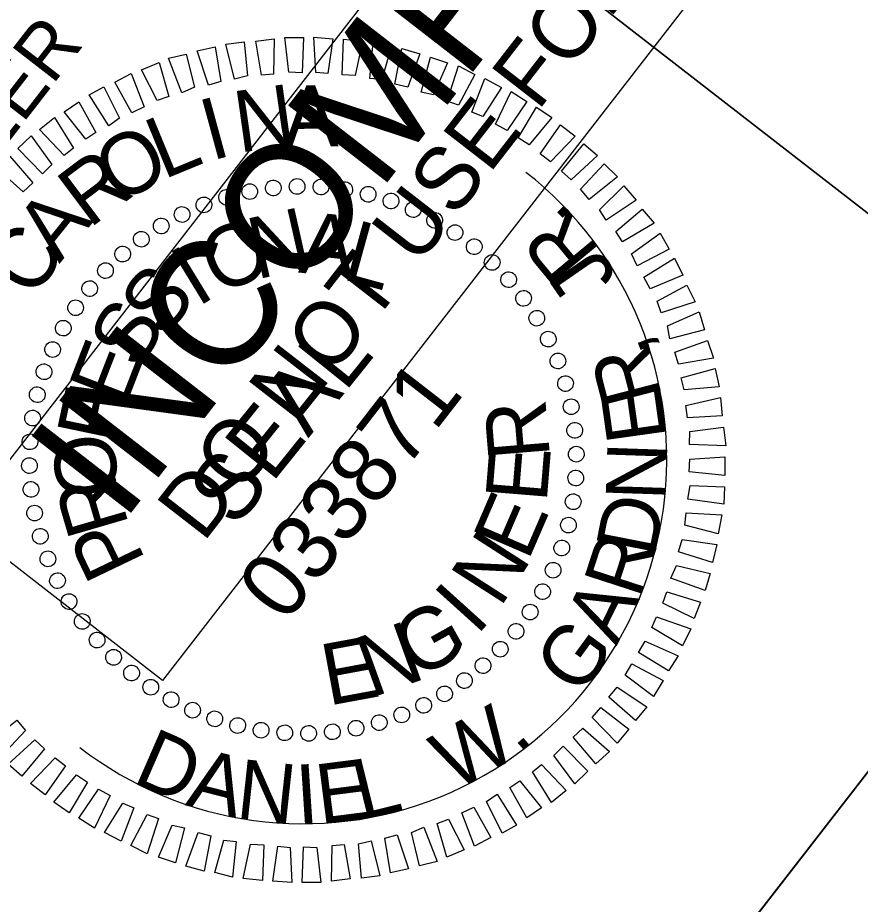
# Model space of a CAD drawing. Extents: x 2013373 to 2015284, y 444589 to 446636.
# Drawn here: x 2014373.4 to 2014450.7, y 446385.3 to 446466.6 of the extents above; entities that cross this region are included whole.
import ezdxf

# ---------------------------------------------------------------- set-up
doc = ezdxf.new("R2010")
doc.units = 0
for name, color, linetype in [('Scratch_Level_0', 7, 'Continuous'), ('Sheet Plan And Profile CELL', 7, 'Continuous'), ('Sheet Professional Seal CELL', 7, 'Continuous'), ('Sheet Profile Grid Minor CELL', 7, 'Continuous'), ('Sheet Sticker Exception Certification CELL', 7, 'Continuous'), ('Sheet Sticker Incomplete CELL', 7, 'Continuous')]:
    doc.layers.add(name, color=color, linetype=linetype)

msp = doc.modelspace()

# ---------------------------------------------------------------- linework, layer by layer
at = {"layer": 'Scratch_Level_0'}
msp.add_arc((2014399.595, 446426.074), 33.364, 232.2051, 52.2051, dxfattribs=at)
at = {"layer": 'Sheet Plan And Profile CELL'}
msp.add_line((2014387.32, 446498.401), (2014476.179, 446429.487), dxfattribs=at)
for points in [[(2014387.32, 446498.401), (2014448.604, 446577.422), (2014537.502, 446508.477), (2014476.219, 446429.457)], [(2014326.006, 446419.34), (2014387.32, 446498.401), (2014476.219, 446429.457), (2014414.904, 446350.396)]]:
    msp.add_lwpolyline(points, close=True, dxfattribs=at)
at = {"layer": 'Sheet Professional Seal CELL'}
for p, q in [((2014394.732, 446450.726), (2014394.732, 446450.726)), ((2014396.867, 446451.032), (2014396.867, 446451.032)), ((2014399.09, 446451.206), (2014399.09, 446451.206)), ((2014401.239, 446451.121), (2014401.239, 446451.121)), ((2014403.445, 446450.865), (2014403.445, 446450.865)), ((2014405.599, 446450.461), (2014405.599, 446450.461)), ((2014392.593, 446450.171), (2014392.593, 446450.171)), ((2014407.67, 446449.867), (2014407.67, 446449.867)), ((2014390.502, 446449.514), (2014390.502, 446449.514)), ((2014409.697, 446449.054), (2014409.697, 446449.054)), ((2014388.517, 446448.586), (2014388.517, 446448.586)), ((2014411.68, 446448.022), (2014411.68, 446448.022)), ((2014386.58, 446447.557), (2014386.58, 446447.557)), ((2014413.563, 446446.942), (2014413.563, 446446.942)), ((2014384.74, 446446.327), (2014384.74, 446446.327)), ((2014415.332, 446445.633), (2014415.332, 446445.633)), ((2014383.097, 446444.943), (2014383.097, 446444.943)), ((2014416.979, 446444.166), (2014416.979, 446444.166)), ((2014381.503, 446443.459), (2014381.503, 446443.459)), ((2014418.463, 446442.572), (2014418.463, 446442.572)), ((2014380.036, 446441.812), (2014380.036, 446441.812)), ((2014419.847, 446440.929), (2014419.847, 446440.929)), ((2014378.727, 446440.043), (2014378.727, 446440.043)), ((2014421.078, 446439.089), (2014421.078, 446439.089)), ((2014377.647, 446438.16), (2014377.647, 446438.16)), ((2014422.106, 446437.152), (2014422.106, 446437.152)), ((2014376.615, 446436.177), (2014376.615, 446436.177)), ((2014423.034, 446435.167), (2014423.034, 446435.167)), ((2014375.802, 446434.15), (2014375.802, 446434.15)), ((2014423.691, 446433.076), (2014423.691, 446433.076)), ((2014375.208, 446432.079), (2014375.208, 446432.079)), ((2014424.246, 446430.937), (2014424.246, 446430.937)), ((2014374.804, 446429.925), (2014374.804, 446429.925)), ((2014424.552, 446428.802), (2014424.552, 446428.802)), ((2014374.548, 446427.719), (2014374.548, 446427.719)), ((2014399.595, 446426.074), (2014399.595, 446426.074)), ((2014424.726, 446426.579), (2014424.726, 446426.579)), ((2014374.463, 446425.57), (2014374.463, 446425.57)), ((2014424.641, 446424.43), (2014424.641, 446424.43)), ((2014374.637, 446423.347), (2014374.637, 446423.347)), ((2014424.386, 446422.224), (2014424.386, 446422.224)), ((2014374.943, 446421.212), (2014374.943, 446421.212)), ((2014423.981, 446420.07), (2014423.981, 446420.07)), ((2014375.498, 446419.073), (2014375.498, 446419.073)), ((2014423.387, 446417.999), (2014423.387, 446417.999)), ((2014376.155, 446416.982), (2014376.155, 446416.982)), ((2014422.575, 446415.972), (2014422.575, 446415.972)), ((2014377.083, 446414.996), (2014377.083, 446414.996)), ((2014421.542, 446413.989), (2014421.542, 446413.989)), ((2014378.112, 446413.06), (2014378.112, 446413.06)), ((2014420.462, 446412.106), (2014420.462, 446412.106)), ((2014379.342, 446411.219), (2014379.342, 446411.219)), ((2014419.153, 446410.337), (2014419.153, 446410.337)), ((2014380.726, 446409.577), (2014380.726, 446409.577)), ((2014417.686, 446408.69), (2014417.686, 446408.69)), ((2014382.21, 446407.983), (2014382.21, 446407.983)), ((2014416.092, 446407.206), (2014416.092, 446407.206)), ((2014383.857, 446406.516), (2014383.857, 446406.516)), ((2014414.45, 446405.822), (2014414.45, 446405.822)), ((2014385.626, 446405.207), (2014385.626, 446405.207)), ((2014387.509, 446404.127), (2014387.509, 446404.127)), ((2014412.609, 446404.592), (2014412.609, 446404.592)), ((2014410.673, 446403.563), (2014410.673, 446403.563)), ((2014389.492, 446403.095), (2014389.492, 446403.095)), ((2014408.687, 446402.635), (2014408.687, 446402.635)), ((2014391.519, 446402.282), (2014391.519, 446402.282)), ((2014393.59, 446401.688), (2014393.59, 446401.688)), ((2014406.597, 446401.978), (2014406.597, 446401.978)), ((2014395.744, 446401.283), (2014395.744, 446401.283)), ((2014397.95, 446401.028), (2014397.95, 446401.028)), ((2014400.099, 446400.943), (2014400.099, 446400.943)), ((2014402.322, 446401.117), (2014402.322, 446401.117)), ((2014404.457, 446401.423), (2014404.457, 446401.423))]:
    msp.add_line(p, q, dxfattribs=at)
for points in [[(2014393.327, 446460.99), (2014392.529, 446464.203), (2014394.213, 446464.416), (2014394.502, 446461.281)], [(2014395.813, 446461.34), (2014395.274, 446464.479), (2014396.958, 446464.692), (2014396.905, 446461.442)], [(2014398.308, 446461.62), (2014397.94, 446464.816), (2014399.65, 446464.819), (2014399.527, 446461.56)], [(2014400.768, 446461.61), (2014400.61, 446464.833), (2014402.338, 446464.695), (2014401.887, 446461.502)], [(2014403.185, 446461.381), (2014403.308, 446464.64), (2014405.075, 446464.471), (2014404.404, 446461.321)], [(2014405.72, 446461.06), (2014406.053, 446464.345), (2014407.676, 446463.909), (2014406.839, 446460.952)], [(2014390.938, 446460.439), (2014389.899, 446463.586), (2014391.565, 446463.939), (2014392.074, 446460.76)], [(2014408.032, 446460.533), (2014408.655, 446463.783), (2014410.317, 446463.316), (2014409.208, 446460.254)], [(2014388.497, 446459.738), (2014387.277, 446462.898), (2014388.904, 446463.282), (2014389.645, 446460.24)], [(2014410.441, 446459.804), (2014411.282, 446463.011), (2014412.844, 446462.495), (2014411.577, 446459.555)], [(2014386.235, 446459.024), (2014384.81, 446461.838), (2014386.401, 446462.502), (2014387.291, 446459.407)], [(2014412.827, 446458.965), (2014413.88, 446462.199), (2014415.367, 446461.424), (2014413.872, 446458.598)], [(2014383.917, 446457.912), (2014382.351, 446460.707), (2014383.854, 446461.503), (2014385.025, 446458.444)], [(2014415.091, 446457.968), (2014416.271, 446461.04), (2014417.798, 446460.235), (2014416.105, 446457.562)], [(2014381.787, 446456.716), (2014380.003, 446459.555), (2014381.335, 446460.294), (2014382.768, 446457.41)], [(2014417.264, 446456.853), (2014418.702, 446459.85), (2014420.138, 446458.927), (2014418.335, 446456.276)], [(2014379.697, 446455.489), (2014377.707, 446457.982), (2014379.052, 446458.9), (2014380.617, 446456.105)], [(2014419.344, 446455.619), (2014421.02, 446458.433), (2014422.424, 446457.47), (2014420.354, 446454.963)], [(2014377.712, 446453.991), (2014375.451, 446456.378), (2014376.809, 446457.476), (2014378.553, 446454.668)], [(2014421.35, 446454.127), (2014423.223, 446456.787), (2014424.567, 446455.745), (2014422.299, 446453.391)], [(2014375.715, 446452.313), (2014373.462, 446454.63), (2014374.671, 446455.781), (2014376.569, 446453.17)], [(2014423.295, 446452.555), (2014425.366, 446455.062), (2014426.608, 446453.972), (2014424.182, 446451.741)], [(2014373.928, 446450.662), (2014371.483, 446452.812), (2014372.731, 446453.932), (2014374.822, 446451.488)], [(2014425.038, 446450.887), (2014427.237, 446453.232), (2014428.457, 446452.032), (2014425.834, 446449.954)], [(2014426.808, 446449.008), (2014429.024, 446451.213), (2014430.153, 446449.894), (2014427.393, 446448.049)], [(2014428.307, 446447.024), (2014430.72, 446449.075), (2014431.809, 446447.787), (2014428.891, 446446.064)], [(2014429.743, 446444.96), (2014432.354, 446446.858), (2014433.181, 446445.395), (2014430.236, 446443.882)], [(2014430.869, 446442.822), (2014433.678, 446444.567), (2014434.443, 446443.024), (2014431.432, 446441.752)], [(2014432.074, 446440.622), (2014434.808, 446442.108), (2014435.573, 446440.565), (2014432.457, 446439.566)], [(2014433.037, 446438.356), (2014435.938, 446439.649), (2014436.432, 446438.001), (2014433.258, 446437.172)], [(2014433.698, 446435.945), (2014436.696, 446437.037), (2014437.26, 446435.398), (2014434.051, 446434.849)], [(2014434.281, 446433.595), (2014437.415, 446434.455), (2014437.768, 446432.789), (2014434.563, 446432.491)], [(2014434.709, 446431.048), (2014437.892, 446431.807), (2014438.035, 446430.114), (2014434.851, 446429.926)], [(2014435.081, 446428.672), (2014438.168, 446429.062), (2014438.381, 446427.378), (2014435.052, 446427.492)], [(2014435.08, 446426.142), (2014438.294, 446426.37), (2014438.297, 446424.659), (2014435.012, 446424.993)], [(2014435.101, 446423.721), (2014438.25, 446423.62), (2014438.204, 446422.011), (2014434.901, 446422.484)], [(2014434.741, 446421.216), (2014438.008, 446421.024), (2014437.69, 446419.309), (2014434.633, 446420.098)], [(2014434.371, 446418.782), (2014437.565, 446418.33), (2014437.168, 446416.677), (2014434.053, 446417.637)], [(2014433.853, 446416.4), (2014436.941, 446415.65), (2014436.496, 446414.097), (2014433.324, 446415.228)], [(2014432.984, 446413.974), (2014436.059, 446413.044), (2014435.465, 446411.543), (2014432.617, 446412.93)], [(2014432.026, 446411.679), (2014435.159, 446410.578), (2014434.394, 446409.02), (2014431.581, 446410.696)], [(2014430.99, 446409.445), (2014434.009, 446408.117), (2014433.117, 446406.721), (2014430.373, 446408.405)], [(2014429.756, 446407.365), (2014432.622, 446405.839), (2014431.738, 446404.373), (2014429.14, 446406.325)], [(2014428.422, 446405.236), (2014431.143, 446403.442), (2014430.093, 446402.169), (2014427.647, 446404.319)], [(2014426.912, 446403.37), (2014429.48, 446401.379), (2014428.429, 446400.106), (2014426.137, 446402.453)], [(2014374.151, 446401.262), (2014371.953, 446398.917), (2014370.732, 446400.117), (2014373.356, 446402.195)], [(2014425.261, 446401.487), (2014427.707, 446399.337), (2014426.458, 446398.217), (2014424.368, 446400.661)], [(2014375.894, 446399.594), (2014373.823, 446397.087), (2014372.581, 446398.177), (2014375.007, 446400.408)], [(2014423.474, 446399.836), (2014425.727, 446397.519), (2014424.518, 446396.368), (2014422.62, 446398.979)], [(2014377.839, 446398.022), (2014375.966, 446395.362), (2014374.622, 446396.404), (2014376.891, 446398.757)], [(2014421.477, 446398.158), (2014423.739, 446395.771), (2014422.381, 446394.672), (2014420.636, 446397.481)], [(2014379.845, 446396.529), (2014378.169, 446393.716), (2014376.765, 446394.679), (2014378.836, 446397.186)], [(2014419.492, 446396.659), (2014421.482, 446394.167), (2014420.137, 446393.249), (2014418.572, 446396.044)], [(2014381.925, 446395.296), (2014380.487, 446392.298), (2014379.052, 446393.222), (2014380.855, 446395.873)], [(2014417.402, 446395.433), (2014419.187, 446392.594), (2014417.855, 446391.855), (2014416.421, 446394.739)], [(2014384.098, 446394.18), (2014382.918, 446391.109), (2014381.391, 446391.914), (2014383.084, 446394.587)], [(2014415.273, 446394.237), (2014416.838, 446391.442), (2014415.335, 446390.646), (2014414.164, 446393.705)], [(2014386.362, 446393.184), (2014385.31, 446389.95), (2014383.822, 446390.724), (2014385.318, 446393.551)], [(2014412.954, 446393.124), (2014414.379, 446390.311), (2014412.788, 446389.647), (2014411.898, 446392.741)], [(2014388.749, 446392.345), (2014387.907, 446389.138), (2014386.345, 446389.654), (2014387.613, 446392.593)], [(2014410.693, 446392.411), (2014411.912, 446389.251), (2014410.285, 446388.867), (2014409.544, 446391.909)], [(2014391.157, 446391.616), (2014390.535, 446388.366), (2014388.872, 446388.833), (2014389.982, 446391.895)], [(2014393.469, 446391.089), (2014393.136, 446387.804), (2014391.513, 446388.24), (2014392.351, 446391.197)], [(2014405.862, 446391.159), (2014406.66, 446387.945), (2014404.976, 446387.733), (2014404.687, 446390.868)], [(2014408.251, 446391.71), (2014409.29, 446388.563), (2014407.624, 446388.21), (2014407.116, 446391.388)], [(2014396.004, 446390.768), (2014395.882, 446387.509), (2014394.114, 446387.678), (2014394.785, 446390.827)], [(2014398.421, 446390.539), (2014398.579, 446387.316), (2014396.851, 446387.454), (2014397.302, 446390.647)], [(2014400.881, 446390.529), (2014401.249, 446387.333), (2014399.539, 446387.33), (2014399.662, 446390.589)], [(2014403.376, 446390.809), (2014403.915, 446387.67), (2014402.232, 446387.457), (2014402.284, 446390.706)]]:
    msp.add_lwpolyline(points, close=True, dxfattribs=at)
for centre, major_axis in [((2014394.721, 446450.676), (-0.14, 0.706)), ((2014396.884, 446451.007), (-0.078, 0.716)), ((2014399.067, 446451.149), (-0.015, 0.72)), ((2014401.255, 446451.099), (0.048, 0.718)), ((2014403.429, 446450.86), (0.11, 0.712)), ((2014392.595, 446450.158), (-0.201, 0.691)), ((2014405.575, 446450.431), (0.172, 0.699)), ((2014407.675, 446449.817), (0.232, 0.682)), ((2014390.523, 446449.456), (-0.26, 0.671)), ((2014409.713, 446449.023), (0.29, 0.659)), ((2014388.52, 446448.577), (-0.318, 0.646)), ((2014411.675, 446448.053), (0.347, 0.631)), ((2014386.601, 446447.526), (-0.373, 0.616)), ((2014413.545, 446446.917), (0.4, 0.598)), ((2014384.78, 446446.312), (-0.425, 0.581)), ((2014415.308, 446445.622), (0.451, 0.561)), ((2014383.073, 446444.944), (-0.474, 0.542)), ((2014416.952, 446444.178), (0.498, 0.52)), ((2014381.491, 446443.432), (-0.52, 0.498)), ((2014418.464, 446442.596), (0.542, 0.474)), ((2014380.047, 446441.788), (-0.561, 0.451)), ((2014419.832, 446440.889), (0.581, 0.425)), ((2014378.752, 446440.024), (-0.598, 0.4)), ((2014421.046, 446439.068), (0.616, 0.373)), ((2014377.616, 446438.155), (-0.631, 0.347)), ((2014422.097, 446437.149), (0.646, 0.318)), ((2014376.647, 446436.193), (-0.659, 0.29)), ((2014422.976, 446435.146), (0.671, 0.26)), ((2014375.852, 446434.155), (-0.682, 0.232)), ((2014423.678, 446433.074), (0.691, 0.201)), ((2014375.238, 446432.055), (-0.699, 0.172)), ((2014424.197, 446430.948), (0.706, 0.14)), ((2014374.809, 446429.909), (-0.712, 0.11)), ((2014424.528, 446428.785), (0.716, 0.078)), ((2014374.57, 446427.734), (-0.718, 0.048)), ((2014424.669, 446426.602), (0.72, 0.015)), ((2014374.52, 446425.547), (-0.72, -0.015)), ((2014424.62, 446424.415), (0.718, -0.048)), ((2014374.662, 446423.364), (-0.716, -0.078)), ((2014424.38, 446422.24), (0.712, -0.11)), ((2014374.993, 446421.201), (-0.706, -0.14)), ((2014423.951, 446420.094), (0.699, -0.172)), ((2014375.511, 446419.075), (-0.691, -0.201)), ((2014423.337, 446417.994), (0.682, -0.232)), ((2014376.213, 446417.003), (-0.671, -0.26)), ((2014422.543, 446415.956), (0.659, -0.29)), ((2014377.092, 446414.999), (-0.646, -0.318)), ((2014421.573, 446413.994), (0.631, -0.347)), ((2014378.143, 446413.08), (-0.616, -0.373)), ((2014420.437, 446412.124), (0.598, -0.4)), ((2014379.357, 446411.26), (-0.581, -0.425)), ((2014419.142, 446410.361), (0.561, -0.451)), ((2014380.726, 446409.553), (-0.542, -0.474)), ((2014417.698, 446408.717), (0.52, -0.498)), ((2014382.237, 446407.971), (-0.498, -0.52)), ((2014416.116, 446407.205), (0.474, -0.542)), ((2014383.881, 446406.527), (-0.451, -0.561)), ((2014414.409, 446405.837), (0.425, -0.581)), ((2014385.645, 446405.232), (-0.4, -0.598)), ((2014412.589, 446404.623), (0.373, -0.616)), ((2014387.514, 446404.096), (-0.347, -0.631)), ((2014410.67, 446403.572), (0.318, -0.646)), ((2014389.476, 446403.126), (-0.29, -0.659)), ((2014408.666, 446402.693), (0.26, -0.671)), ((2014391.514, 446402.332), (-0.232, -0.682)), ((2014393.614, 446401.718), (-0.172, -0.699)), ((2014406.594, 446401.991), (0.201, -0.691)), ((2014395.76, 446401.289), (-0.11, -0.712)), ((2014397.935, 446401.049), (-0.048, -0.718)), ((2014400.122, 446401), (0.015, -0.72)), ((2014402.305, 446401.141), (0.078, -0.716)), ((2014404.468, 446401.473), (0.14, -0.706))]:
    msp.add_ellipse(centre, major_axis=major_axis, ratio=0.999708, dxfattribs=at)
at = {"layer": 'Sheet Sticker Exception Certification CELL'}
msp.add_line((2014414.891, 446350.406), (2014537.489, 446508.488), dxfattribs=at)
at = {"layer": 'Sheet Sticker Incomplete CELL'}
msp.add_lwpolyline([(2014386.726, 446405.848), (2014368.156, 446420.25), (2014458.243, 446536.411), (2014476.813, 446522.009)], close=True, dxfattribs=at)

# ---------------------------------------------------------------- texts
at = {"layer": 'Sheet Plan And Profile CELL'}
for s, p in [('ROADWAY DESIGN', (2014343.663, 446430.197)), ('ENGINEER', (2014358.179, 446436.593))]:
    msp.add_text(s, height=5.0001, rotation=52.2051, dxfattribs=at).set_placement(p)
at = {"layer": 'Sheet Professional Seal CELL'}
for s, height, rotation, p in [('N', 5.639, 8.02401, (2014393.718, 446454.233)), ('A', 5.639, 0.82226, (2014397.857, 446454.756)), ('I', 5.638, 15.22525, (2014391.176, 446453.484)), ('L', 5.638, 22.42598, (2014386.797, 446451.754)), ('O', 5.638, 29.62627, (2014382.639, 446449.411)), ('R', 5.638, 36.8262, (2014379.993, 446447.224)), ('A', 5.638, 51.22542, (2014377.262, 446444.027)), ('N', 5.638, 12.68171, (2014395.331, 446442.605)), ('A', 5.639, 353.96537, (2014399.132, 446443.264)), ('C', 5.638, 58.42497, (2014375.078, 446440.722)), ('O', 5.638, 22.03859, (2014391.697, 446441.184)), ('L', 5.639, 344.60595, (2014403.053, 446442.691)), ('I', 5.638, 31.39471, (2014389.919, 446440.032)), ('S', 5.638, 50.1055, (2014386.73, 446437.064)), ('S', 5.638, 59.46071, (2014384.564, 446434.188)), ('E', 5.638, 68.81617, (2014383.279, 446430.818)), ('SEAL', 5.9982, 51.2051, (2014393.381, 446419.694)), ('F', 5.638, 78.17214, (2014382.503, 446427.371)), ('R', 5.639, 94.68651, (2014422.262, 446426.339)), ('O', 5.639, 96.88634, (2014382.812, 446422.955)), ('E', 5.638, 85.32919, (2014421.943, 446422.093)), ('R', 5.639, 106.24475, (2014383.676, 446420.071)), ('E', 5.638, 66.61686, (2014420.236, 446416.71)), ('P', 5.639, 115.60399, (2014385.224, 446416.845)), ('N', 5.638, 57.26149, (2014417.677, 446412.431)), ('I', 5.638, 47.9063, (2014415.505, 446409.875)), ('G', 5.638, 29.19534, (2014409.99, 446405.864)), ('N', 5.639, 19.83906, (2014405.883, 446404.24)), ('E', 5.638, 10.48199, (2014401.911, 446403.524))]:
    msp.add_text(s, height=height, rotation=rotation, dxfattribs=at).set_placement(p)
at = {"layer": 'Sheet Profile Grid Minor CELL'}
for s, height, rotation, p in [('R', 5.5, 129.55916, (2014427.013, 446445.27)), ('.', 5.5, 136.4856, (2014424.498, 446448.437)), ('J', 5.5, 124.69061, (2014428.543, 446442.874)), ('R', 5.5, 104.58389, (2014432.554, 446431.899)), (',', 5.5, 111.51034, (2014431.611, 446435.831)), ('033871', 5.9982, 52.2051, (2014398.018, 446410.974)), ('E', 5.5, 98.00091, (2014433.004, 446428.082)), ('N', 5.5, 88.06919, (2014432.85, 446422.289)), ('D', 5.5, 78.92457, (2014431.826, 446417.052)), ('R', 5.5, 71.99813, (2014430.502, 446413.231)), ('A', 5.5, 63.81233, (2014428.359, 446408.961)), ('G', 5.5, 53.88061, (2014424.976, 446404.257)), ('W', 5.5, 29.09425, (2014413.491, 446395.626)), ('D', 5.5, 336.47332, (2014383.835, 446396.547)), ('.', 5.5, 40.70034, (2014419.333, 446399.044)), ('A', 5.5, 345.61794, (2014388.728, 446394.417)), ('N', 5.5, 353.80374, (2014393.347, 446393.193)), ('E', 5.5, 7.25592, (2014401.167, 446392.641)), ('L', 5.5, 13.8389, (2014404.99, 446393.042)), ('I', 5.5, 3.73545, (2014399.111, 446392.608))]:
    msp.add_text(s, height=height, rotation=rotation, dxfattribs=at).set_placement(p)
at = {"layer": 'Sheet Sticker Exception Certification CELL'}
for s, p in [('DOCUMENT NOT CONSIDERED FINAL', (2014433.141, 446350.965)), ('UNLESS ALL SIGNATURES COMPLETED', (2014437.738, 446340.146))]:
    msp.add_text(s, height=6.12398, rotation=52.2051, dxfattribs=at).set_placement(p)
at = {"layer": 'Sheet Sticker Incomplete CELL'}
for s, height, p in [('INCOMPLETE PLANS', 11.52, (2014382.965, 446420.091)), ('DO NOT USE FOR R/W ACQUISITION', 5.76, (2014390.449, 446418.4))]:
    msp.add_text(s, height=height, rotation=52.2051, dxfattribs=at).set_placement(p)

doc.saveas('drawing.dxf')
